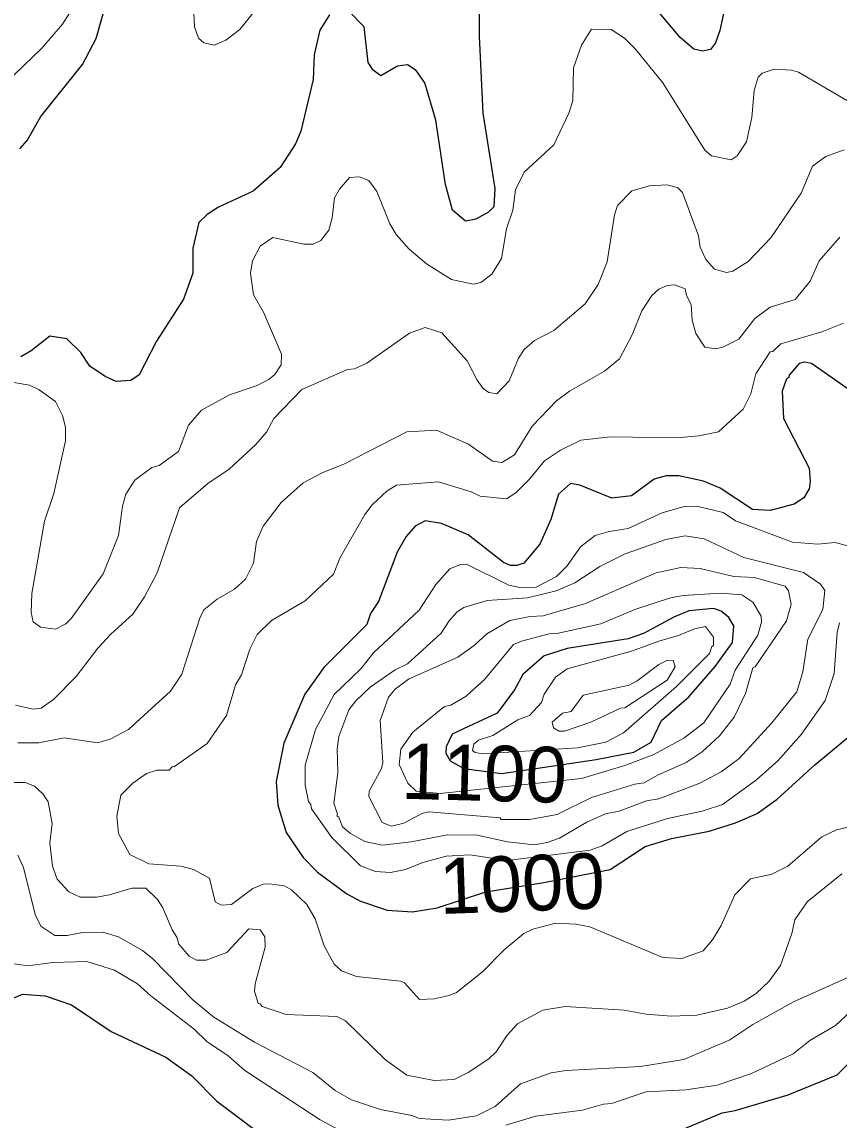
# Model space of a CAD drawing. Extents: x 598.3 to 623.2, y 6902.2 to 6930.1.
# Drawn here: x 621.002 to 622.178, y 6913.109 to 6914.688 of the extents above; entities that cross this region are included whole.
import ezdxf
from ezdxf.enums import TextEntityAlignment as Align

# ---------------------------------------------------------------- set-up
doc = ezdxf.new("R2010")
doc.units = 0
doc.header["$LTSCALE"] = 0.032
doc.layers.add('1', color=7, linetype='Continuous', lineweight=25)
doc.layers.add('2', color=7, linetype='Continuous', lineweight=13)
doc.layers.add('61', color=7, linetype='Continuous')

msp = doc.modelspace()

# ---------------------------------------------------------------- linework, layer by layer
at = {"layer": '1'}
for points in [[(620.9987, 6914.5057), (621.0092, 6914.5179), (621.0292, 6914.5525), (621.0891, 6914.6269), (621.1087, 6914.6646), (621.1344, 6914.7565), (621.144, 6914.8643), (621.1555, 6914.9022)], [(621.6605, 6914.7606), (621.6597, 6914.668), (621.6653, 6914.5573), (621.6823, 6914.4489), (621.6808, 6914.4226), (621.6734, 6914.4146), (621.6549, 6914.4045), (621.6401, 6914.4017), (621.6217, 6914.4178), (621.6112, 6914.4547), (621.5974, 6914.547), (621.5819, 6914.6007), (621.569, 6914.6185), (621.5568, 6914.6265), (621.5421, 6914.6248), (621.5182, 6914.6106), (621.5071, 6914.6189), (621.5, 6914.6301), (621.4943, 6914.6811), (621.4713, 6914.7049)], [(622.0172, 6914.7279), (622.0063, 6914.6759), (621.9999, 6914.6581), (621.9928, 6914.6485), (621.9813, 6914.6461), (621.9689, 6914.6494), (621.9489, 6914.6661), (621.8643, 6914.7678)], [(621.4444, 6914.6987), (621.4305, 6914.6765), (621.4224, 6914.6409), (621.4208, 6914.6053), (621.4031, 6914.5314), (621.3956, 6914.5131), (621.3736, 6914.4791), (621.3345, 6914.445), (621.2847, 6914.4217), (621.2686, 6914.4113), (621.2566, 6914.3999), (621.2477, 6914.363), (621.2476, 6914.3271), (621.2344, 6914.2896), (621.1957, 6914.229), (621.1708, 6914.1809), (621.1586, 6914.1725), (621.1376, 6914.171), (621.1216, 6914.1781), (621.0998, 6914.1934), (621.0867, 6914.2128), (621.0663, 6914.2324), (621.0418, 6914.2362), (621.015, 6914.2153), (621.0002, 6914.2067)], [(622.1922, 6914.1593), (622.1381, 6914.1968), (622.1281, 6914.1991), (622.1205, 6914.1969), (622.1059, 6914.1801), (622.1056, 6914.1767), (622.1022, 6914.1751), (622.096, 6914.1571), (622.0979, 6914.1177), (622.1349, 6914.0463), (622.1364, 6914.0274), (622.1348, 6914.0166), (622.127, 6914.0037), (622.1132, 6913.9946), (622.0784, 6913.9856), (622.0533, 6913.9871), (622.0069, 6914.0179), (621.9829, 6914.028), (621.9473, 6914.0357), (621.9292, 6914.0357), (621.9117, 6914.0309), (621.879, 6914.0066), (621.851, 6914.0035), (621.8048, 6914.0218), (621.7914, 6914.0243), (621.7738, 6914.009), (621.7632, 6913.9726), (621.7473, 6913.9373), (621.724, 6913.9099), (621.7139, 6913.9063), (621.705, 6913.9063), (621.6948, 6913.9109), (621.6442, 6913.9507), (621.6057, 6913.9668)], [(621.6057, 6913.9668), (621.5822, 6913.9709), (621.5677, 6913.9632), (621.5548, 6913.9484), (621.5419, 6913.9257), (621.5151, 6913.8546), (621.5036, 6913.8375), (621.4983, 6913.8218), (621.4362, 6913.7597), (621.409, 6913.7214), (621.379, 6913.6511), (621.3675, 6913.5957), (621.3699, 6913.5618), (621.3822, 6913.5223), (621.4066, 6913.4864), (621.4272, 6913.4653), (621.4692, 6913.4344), (621.4891, 6913.4236), (621.5274, 6913.4109), (621.564, 6913.4084), (621.5992, 6913.4141), (621.6693, 6913.4369)], [(621.9532, 6913.0958), (622.0096, 6913.1194), (622.0283, 6913.1227), (622.1044, 6913.1449), (622.1752, 6913.1737), (622.2152, 6913.2135), (622.2708, 6913.2594), (622.2876, 6913.2706), (622.3587, 6913.3055), (622.3878, 6913.3258), (622.4063, 6913.3423), (622.4173, 6913.3606), (622.4224, 6913.3803), (622.4418, 6913.4192), (622.4883, 6913.4769), (622.5215, 6913.5084), (622.5709, 6913.5416), (622.6138, 6913.5812), (622.6613, 6913.6168), (622.6744, 6913.6315), (622.699, 6913.6667), (622.7232, 6913.7247)], [(621.6693, 6913.4369), (621.753, 6913.4505), (621.8485, 6913.469), (621.8987, 6913.5023), (621.9364, 6913.5138), (621.991, 6913.5242), (622.0286, 6913.5362), (622.0601, 6913.5499), (622.0886, 6913.5705), (622.1429, 6913.6196), (622.2017, 6913.6688)], [(620.68, 6913.0989), (620.7007, 6913.1139), (620.7193, 6913.1227), (620.759, 6913.1292), (620.7998, 6913.1439), (620.8346, 6913.1622), (620.8836, 6913.1997), (620.9378, 6913.2539), (620.977, 6913.2787), (621.0026, 6913.2901), (621.0353, 6913.2874), (621.0731, 6913.2747), (621.1304, 6913.2363), (621.2091, 6913.1994), (621.2463, 6913.1726), (621.2823, 6913.1358), (621.3652, 6913.0739)]]:
    msp.add_lwpolyline(points, dxfattribs=at)
msp.add_lwpolyline([(621.6122, 6913.6457), (621.6118, 6913.6367), (621.6182, 6913.6255), (621.6379, 6913.6147), (621.6923, 6913.6074), (621.8282, 6913.6274), (621.8825, 6913.6379), (621.9073, 6913.6524), (621.9222, 6913.6836), (621.9614, 6913.7174), (621.9994, 6913.7611), (622.0245, 6913.7959), (622.0261, 6913.8199), (622.0192, 6913.8315), (622.0083, 6913.841), (621.9972, 6913.8446), (621.9617, 6913.8414), (621.9398, 6913.8322), (621.8965, 6913.8089), (621.8745, 6913.801), (621.7867, 6913.7872), (621.7536, 6913.7766), (621.7228, 6913.7499), (621.7108, 6913.7276), (621.686, 6913.694), (621.6444, 6913.6747), (621.6212, 6913.6639)], close=True, dxfattribs=at)
at = {"layer": '2'}
for points in [[(621.0646, 6914.8015), (621.0889, 6914.7623), (621.0882, 6914.737), (621.0806, 6914.7168), (621.0602, 6914.6852), (621.0304, 6914.6506), (620.9772, 6914.5991)], [(621.3496, 6914.7206), (621.3156, 6914.6776), (621.2955, 6914.6619), (621.2784, 6914.655), (621.2634, 6914.6584), (621.2558, 6914.6652), (621.2501, 6914.6815), (621.2493, 6914.7014)], [(620.9736, 6914.1726), (621.0129, 6914.166), (621.0269, 6914.159), (621.05, 6914.1425), (621.0602, 6914.1223), (621.0647, 6914.1056), (621.0646, 6914.0857), (621.0477, 6914.0101), (621.0345, 6913.9701), (621.0162, 6913.8663), (621.0154, 6913.8389), (621.0178, 6913.8253), (621.0284, 6913.818), (621.0504, 6913.8149), (621.0652, 6913.8227), (621.0734, 6913.8309), (621.1188, 6913.8947), (621.1407, 6913.9497), (621.1464, 6913.9918), (621.1513, 6914.0092), (621.1642, 6914.0292), (621.1888, 6914.0475), (621.1996, 6914.0505), (621.2272, 6914.0706), (621.2418, 6914.1084), (621.2605, 6914.1299), (621.3005, 6914.152), (621.3405, 6914.1655), (621.3576, 6914.1744), (621.3657, 6914.1813), (621.375, 6914.1953), (621.3754, 6914.2107), (621.3494, 6914.2711), (621.3351, 6914.2958), (621.331, 6914.3272), (621.3335, 6914.3449), (621.3447, 6914.3658), (621.3629, 6914.3781), (621.4074, 6914.3685), (621.4211, 6914.3685), (621.4319, 6914.374), (621.4436, 6914.3889), (621.4483, 6914.4065), (621.4517, 6914.4353), (621.4591, 6914.4478), (621.4734, 6914.4645), (621.4872, 6914.4655), (621.5013, 6914.4602), (621.5128, 6914.4442), (621.5312, 6914.3979), (621.5403, 6914.3827), (621.5589, 6914.3615), (621.5842, 6914.3402), (621.6202, 6914.3181), (621.6511, 6914.3113), (621.6623, 6914.3135), (621.6781, 6914.3256), (621.6922, 6914.3479), (621.6994, 6914.3906), (621.7082, 6914.4176), (621.7122, 6914.4467), (621.7247, 6914.4722), (621.7673, 6914.5118), (621.789, 6914.5569), (621.7948, 6914.5748), (621.7957, 6914.6221), (621.8073, 6914.6551), (621.8217, 6914.6779), (621.85, 6914.6775), (621.8689, 6914.6651), (621.8846, 6914.6493), (621.9243, 6914.6007), (621.9845, 6914.5041)], [(621.9845, 6914.5041), (621.9941, 6914.4956), (622.0227, 6914.49), (622.0311, 6914.4956), (622.0445, 6914.5158), (622.0523, 6914.5508), (622.0555, 6914.5897), (622.0612, 6914.6088), (622.0669, 6914.6145), (622.0844, 6914.6203), (622.1095, 6914.6192), (622.1194, 6914.6161), (622.19, 6914.575)], [(622.185, 6914.5044), (622.1589, 6914.4946), (622.1397, 6914.4809), (622.1234, 6914.4419), (622.0798, 6914.378), (622.0471, 6914.3437), (622.0247, 6914.3297), (622.0157, 6914.3281), (621.9986, 6914.3325), (621.986, 6914.3464), (621.9777, 6914.3644), (621.9753, 6914.3806), (621.9525, 6914.443), (621.9454, 6914.4501), (621.9298, 6914.4542), (621.9049, 6914.4526), (621.8795, 6914.4456), (621.8589, 6914.4241), (621.8547, 6914.4111), (621.8442, 6914.3431), (621.8311, 6914.3107), (621.8122, 6914.2831), (621.7675, 6914.2447), (621.7396, 6914.2299), (621.7247, 6914.2173), (621.7166, 6914.2047), (621.7028, 6914.1722), (621.6853, 6914.1532), (621.6737, 6914.1555), (621.6657, 6914.161), (621.6569, 6914.173), (621.6426, 6914.2008), (621.606, 6914.2413), (621.582, 6914.2487), (621.5594, 6914.2409), (621.4981, 6914.1974), (621.4805, 6914.1895), (621.4705, 6914.1885), (621.4045, 6914.1596), (621.3646, 6914.1178), (621.354, 6914.0984), (621.3385, 6914.0804), (621.3001, 6914.0452), (621.2695, 6914.0246), (621.2285, 6913.9893), (621.1964, 6913.896), (621.1782, 6913.8612), (621.1616, 6913.8366), (621.1296, 6913.8076), (621.111, 6913.7874), (621.08, 6913.7467), (621.0473, 6913.7139), (621.0296, 6913.7015), (621.0176, 6913.6999), (620.9927, 6913.7058)], [(622.1791, 6914.3787), (622.1492, 6914.3447), (622.1363, 6914.3156), (622.1146, 6914.2892), (622.0785, 6914.2779), (622.0567, 6914.2619), (622.0334, 6914.2321), (622.0114, 6914.221), (622.0004, 6914.218), (621.9845, 6914.2204), (621.9718, 6914.2401), (621.9664, 6914.2594), (621.9648, 6914.2818), (621.9583, 6914.295), (621.9565, 6914.3043), (621.9411, 6914.3101), (621.9303, 6914.3092), (621.9183, 6914.3039), (621.9083, 6914.2949), (621.8938, 6914.2727), (621.8798, 6914.2381), (621.8616, 6914.2037), (621.8404, 6914.1859), (621.7898, 6914.1572), (621.7713, 6914.1432), (621.7361, 6914.1071), (621.7106, 6914.0658), (621.6926, 6914.0547), (621.6789, 6914.0565), (621.6446, 6914.0809), (621.5986, 6914.1013), (621.556, 6914.0988), (621.4652, 6914.0522), (621.4349, 6914.0403), (621.4066, 6914.0254), (621.3747, 6913.9969), (621.3488, 6913.9629), (621.3393, 6913.9408), (621.3351, 6913.91), (621.3235, 6913.8866), (621.3077, 6913.8725), (621.283, 6913.8583), (621.2635, 6913.8425), (621.2578, 6913.8307), (621.2318, 6913.7502), (621.2158, 6913.7258), (621.1551, 6913.6705), (621.13, 6913.6571), (621.1111, 6913.6513), (621.0626, 6913.6586), (621.0264, 6913.6513), (620.996, 6913.6513)], [(621.33, 6913.7862), (621.3406, 6913.8072), (621.3609, 6913.8276), (621.4093, 6913.8559), (621.45, 6913.894), (621.4595, 6913.9169), (621.4953, 6913.9799), (621.5058, 6913.9936), (621.5277, 6914.0138), (621.5409, 6914.0219), (621.6011, 6914.0269), (621.6482, 6914.0126), (621.6615, 6914.0063), (621.6991, 6914.0026), (621.7128, 6914.0111), (621.7323, 6914.0306), (621.7538, 6914.0569), (621.7767, 6914.0724), (621.8064, 6914.0868), (621.8488, 6914.0916), (621.9444, 6914.09), (621.9762, 6914.0932), (622.0044, 6914.0989), (622.0399, 6914.1314), (622.051, 6914.1533), (622.0582, 6914.182), (622.0788, 6914.2136), (622.0824, 6914.2141), (622.0938, 6914.2252), (622.1532, 6914.2424), (622.184, 6914.255)], [(622.19, 6913.9347), (622.172, 6913.9394), (622.1469, 6913.937), (622.1108, 6913.9402), (622.0285, 6913.9707), (622.0108, 6913.9828), (621.9729, 6913.992), (621.9549, 6913.9912), (621.923, 6913.9823), (621.8745, 6913.9597), (621.8469, 6913.9556), (621.827, 6913.9498), (621.8055, 6913.9331), (621.7866, 6913.906), (621.771, 6913.8905), (621.7417, 6913.8755), (621.7182, 6913.875), (621.7027, 6913.8783), (621.6416, 6913.9085), (621.633, 6913.9078), (621.6176, 6913.9017), (621.5977, 6913.8792), (621.5737, 6913.8422), (621.5076, 6913.7809), (621.4895, 6913.758), (621.4513, 6913.7207), (621.4244, 6913.6707), (621.4095, 6913.6194), (621.4095, 6913.5905), (621.4141, 6913.5671), (621.4176, 6913.5628), (621.4185, 6913.5567), (621.4479, 6913.5152), (621.489, 6913.4745), (621.5108, 6913.4664), (621.5322, 6913.465), (621.5539, 6913.4691), (621.579, 6913.4794), (621.6122, 6913.4886), (621.6465, 6913.4901), (621.7006, 6913.4821), (621.8194, 6913.4969), (621.8367, 6913.5035), (621.8725, 6913.5241), (621.9311, 6913.5428), (621.9808, 6913.5532), (622.0099, 6913.5629), (622.0589, 6913.5982), (622.0897, 6913.6255), (622.1238, 6913.664), (622.1577, 6913.7125), (622.1705, 6913.7511), (622.1752, 6913.8101), (622.1786, 6913.8242)], [(622.2141, 6913.5355), (622.1743, 6913.5262), (622.1529, 6913.5162), (622.1039, 6913.4738), (622.0808, 6913.4626), (622.0504, 6913.4558), (622.0278, 6913.4327), (622.008, 6913.3887), (621.9954, 6913.3681), (621.982, 6913.352), (621.9517, 6913.3411), (621.9242, 6913.3425), (621.8189, 6913.3866), (621.7992, 6913.3906), (621.7703, 6913.3921), (621.7371, 6913.3834), (621.7242, 6913.377), (621.6959, 6913.3539), (621.6645, 6913.3218), (621.6271, 6913.2925), (621.6168, 6913.2878), (621.5951, 6913.283), (621.5741, 6913.2821), (621.5523, 6913.3061), (621.5467, 6913.3088), (621.4835, 6913.3153), (621.4619, 6913.3235), (621.4511, 6913.333), (621.4369, 6913.3595), (621.4239, 6913.3984), (621.4121, 6913.4187), (621.39, 6913.4399), (621.3791, 6913.4455), (621.3577, 6913.4488), (621.3489, 6913.448), (621.334, 6913.4417), (621.3036, 6913.4188), (621.2884, 6913.4181), (621.2799, 6913.4227), (621.2718, 6913.4569), (621.249, 6913.4691), (621.2304, 6913.4738), (621.1845, 6913.4772), (621.157, 6913.491), (621.1406, 6913.521), (621.1384, 6913.5459), (621.1441, 6913.5759), (621.1616, 6913.5935), (621.1813, 6913.6073), (621.1958, 6913.6123), (621.2138, 6913.612), (621.2181, 6913.6169), (621.2215, 6913.6173), (621.2684, 6913.6503), (621.2961, 6913.6909), (621.3093, 6913.7346), (621.3179, 6913.749), (621.33, 6913.7862)], [(620.977, 6913.5945), (621.0064, 6913.5945), (621.0198, 6913.5893), (621.0321, 6913.5779), (621.0397, 6913.5664), (621.0452, 6913.5352), (621.042, 6913.507), (621.046, 6913.4742), (621.0526, 6913.4555), (621.0692, 6913.437), (621.0857, 6913.4295), (621.109, 6913.4295), (621.1281, 6913.4327), (621.16, 6913.4423), (621.1803, 6913.4422), (621.197, 6913.4259), (621.2046, 6913.4143), (621.2182, 6913.3822), (621.2249, 6913.372), (621.2278, 6913.3617), (621.2427, 6913.3447), (621.2533, 6913.3388), (621.267, 6913.3388), (621.2965, 6913.35), (621.3285, 6913.3838), (621.3446, 6913.3824), (621.3512, 6913.3724), (621.352, 6913.3574), (621.3374, 6913.305), (621.3367, 6913.294), (621.3418, 6913.2765), (621.3448, 6913.2762), (621.3475, 6913.2723), (621.3819, 6913.2607), (621.4551, 6913.2577), (621.4674, 6913.2517), (621.5251, 6913.1956), (621.5557, 6913.1732), (621.5951, 6913.1656), (621.624, 6913.1672), (621.6442, 6913.177), (621.6737, 6913.1967), (621.6841, 6913.2071), (621.7, 6913.2311), (621.715, 6913.247), (621.7514, 6913.2668), (621.7835, 6913.2723), (621.8683, 6913.2667), (621.9, 6913.2612), (621.9367, 6913.2582), (621.9732, 6913.2595), (622.0172, 6913.2696), (622.0412, 6913.2798), (622.0585, 6913.2909), (622.0771, 6913.3086), (622.0934, 6913.3313), (622.1099, 6913.3774), (622.1141, 6913.397), (622.1317, 6913.4229), (622.1819, 6913.4631)], [(620.9959, 6913.4898), (621.004, 6913.4721), (621.0209, 6913.4043), (621.0292, 6913.3879), (621.0493, 6913.3744), (621.0669, 6913.3744), (621.089, 6913.3784), (621.1181, 6913.3792), (621.141, 6913.3726), (621.1754, 6913.3527), (621.1904, 6913.3409), (621.2482, 6913.2814), (621.2781, 6913.2566), (621.3364, 6913.221), (621.4206, 6913.177), (621.4527, 6913.1513), (621.4762, 6913.1379), (621.518, 6913.1242), (621.563, 6913.1153), (621.5739, 6913.1111), (621.6152, 6913.1089), (621.6562, 6913.1148), (621.6829, 6913.1282), (621.7193, 6913.1609), (621.7635, 6913.1767), (621.7846, 6913.1801), (621.8918, 6913.1857), (621.9545, 6913.1958), (622.0205, 6913.2241), (622.0537, 6913.2465), (622.1121, 6913.2788), (622.2523, 6913.3417)], [(620.9844, 6913.3344), (621.0103, 6913.3306), (621.0463, 6913.3355), (621.0954, 6913.3371), (621.1349, 6913.3246), (621.1681, 6913.3049), (621.1874, 6913.2873), (621.2495, 6913.2395), (621.2678, 6913.222), (621.2986, 6913.201), (621.3224, 6913.1799), (621.4311, 6913.1093), (621.4713, 6913.0877)], [(621.698, 6913.1016), (621.7412, 6913.1145), (621.8085, 6913.1232), (621.8386, 6913.1315), (621.8505, 6913.1325), (621.9001, 6913.1493), (621.9574, 6913.1524), (622.0024, 6913.1591), (622.0516, 6913.1756), (622.1119, 6913.2042), (622.1358, 6913.2232), (622.1725, 6913.245), (622.2146, 6913.2839)]]:
    msp.add_lwpolyline(points, dxfattribs=at)
for points in [[(621.6283, 6913.8399), (621.638, 6913.8463), (621.6716, 6913.856), (621.7292, 6913.8599), (621.7708, 6913.87), (621.7973, 6913.8817), (621.8333, 6913.9051), (621.8699, 6913.9233), (621.9283, 6913.944), (621.9562, 6913.9491), (621.9835, 6913.9447), (622.0408, 6913.9179), (622.1265, 6913.8965), (622.151, 6913.8794), (622.1574, 6913.8703), (622.1543, 6913.8434), (622.1326, 6913.8004), (622.1258, 6913.7535), (622.1169, 6913.7247), (622.0809, 6913.6801), (622.0341, 6913.6289), (622.0083, 6913.6099), (621.9776, 6913.5936), (621.9182, 6913.5711), (621.9007, 6913.568), (621.8612, 6913.5532), (621.8418, 6913.5492), (621.8148, 6913.5373), (621.7757, 6913.5142), (621.7579, 6913.508), (621.7388, 6913.5047), (621.7008, 6913.5092), (621.657, 6913.5185), (621.6142, 6913.5193), (621.5618, 6913.5092), (621.5203, 6913.504), (621.4953, 6913.5096), (621.4749, 6913.521), (621.4632, 6913.5306), (621.4581, 6913.5443), (621.4551, 6913.5466), (621.4562, 6913.549), (621.4509, 6913.5644), (621.4564, 6913.6083), (621.4557, 6913.6427), (621.4581, 6913.6604), (621.4725, 6913.6988), (621.4824, 6913.7119), (621.5029, 6913.7315), (621.5388, 6913.7563), (621.5566, 6913.7652), (621.6053, 6913.809), (621.6166, 6913.8267)], [(621.6525, 6913.7912), (621.6708, 6913.8081), (621.7042, 6913.8276), (621.7333, 6913.8333), (621.7518, 6913.8339), (621.8129, 6913.852), (621.9144, 6913.8957), (621.95, 6913.9037), (621.9778, 6913.9021), (622.0261, 6913.8909), (622.0558, 6913.8892), (622.1001, 6913.8767), (622.105, 6913.87), (622.1089, 6913.8511), (622.1023, 6913.8268), (622.0571, 6913.7607), (622.0538, 6913.7594), (622.0429, 6913.7226), (622.0266, 6913.6881), (622.0057, 6913.6613), (621.9806, 6913.6386), (621.9576, 6913.6233), (621.9163, 6913.605), (621.8975, 6913.5941), (621.8838, 6913.5919), (621.8217, 6913.573), (621.7722, 6913.5484), (621.7324, 6913.541), (621.6915, 6913.5412), (621.6899, 6913.5436), (621.5874, 6913.5524), (621.5774, 6913.5498), (621.5513, 6913.5358), (621.5338, 6913.5315), (621.5201, 6913.5367), (621.5011, 6913.5741), (621.5018, 6913.5821), (621.5195, 6913.6146), (621.5213, 6913.6232), (621.5172, 6913.6836), (621.5295, 6913.717), (621.539, 6913.7288), (621.5581, 6913.743), (621.629, 6913.7746)], [(621.5473, 6913.6423), (621.5643, 6913.6667), (621.6099, 6913.7035), (621.6189, 6913.7057), (621.641, 6913.7185), (621.6681, 6913.7431), (621.7091, 6913.7927), (621.7207, 6913.7978), (621.7608, 6913.8082), (621.7716, 6913.8087), (621.8348, 6913.8227), (621.8839, 6913.843), (621.9352, 6913.8601), (621.9533, 6913.8633), (622.0073, 6913.8666), (622.0377, 6913.8641), (622.0537, 6913.8538), (622.0659, 6913.8336), (622.066, 6913.8252), (622.0611, 6913.8061), (622.0281, 6913.7559), (622.0213, 6913.736), (621.983, 6913.68), (621.9545, 6913.6579), (621.9101, 6913.634), (621.8694, 6913.6189), (621.8073, 6913.6003), (621.6039, 6913.5787), (621.5694, 6913.5817), (621.5574, 6913.5933), (621.5447, 6913.6203)], [(621.9699, 6913.8156), (621.9858, 6913.8186), (621.9971, 6913.8033), (621.9972, 6913.7915), (621.9947, 6913.7902), (621.9915, 6913.78), (621.944, 6913.7323), (621.8675, 6913.6656), (621.8421, 6913.6522), (621.8013, 6913.644), (621.6646, 6913.6357), (621.654, 6913.6376), (621.6504, 6913.6405), (621.6521, 6913.6493), (621.6591, 6913.6551), (621.6793, 6913.6622), (621.7155, 6913.6844), (621.7325, 6913.6909), (621.7495, 6913.7096), (621.7534, 6913.7214), (621.7695, 6913.7457), (621.7865, 6913.7579), (621.8793, 6913.7832), (621.9182, 6913.7978), (621.9468, 6913.8057)], [(621.8632, 6913.7014), (621.8697, 6913.7016), (621.9304, 6913.7416), (621.9421, 6913.7607), (621.939, 6913.7699), (621.9309, 6913.7702), (621.9184, 6913.764), (621.8874, 6913.7407), (621.8756, 6913.7344), (621.8096, 6913.72), (621.7924, 6913.6967), (621.78, 6913.694), (621.765, 6913.6811), (621.7667, 6913.673), (621.7752, 6913.6684), (621.7827, 6913.6683), (621.8205, 6913.681)]]:
    msp.add_lwpolyline(points, close=True, dxfattribs=at)

# ---------------------------------------------------------------- texts
at = {"layer": '61'}
for s, rotation, p in [('1100', 358.531, (621.6661, 6913.568)), ('1000', 2.01, (621.7227, 6913.4093))]:
    msp.add_text(s, height=0.08, rotation=rotation, dxfattribs=at).set_placement(p, align=Align.CENTER)

doc.saveas('drawing.dxf')
